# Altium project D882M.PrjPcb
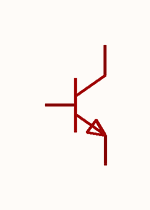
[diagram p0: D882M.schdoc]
1 sheet, 1 parts. Net scope: global (net labels, ports and power ports of the same name join across sheets).

## Sheet D882M.schdoc
size 127 x 101 mm

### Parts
Q?  d882m(range:160-320)  [TO-252-2_L6.5-W6.1-P4.58-LS10.0-TL]  (value not drawn)

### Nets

Not connected (* = marked no-connect by the designer): Q? 1(B) 3(E) 4(C)

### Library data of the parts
Q? = d882m(range:160-320): 晶体管类型:NPN;集电极电流(Ic):3A;集射极击穿电压(Vceo):30V;耗散功率(Pd):1.25W;直流电流增益(hFE):160;; Manufacturer: CJ(江苏长电/长晶); AddInBom: yes; ModelId: 6b2ea0154a284e6db98f69bccdba3606; ModelName: TO-252-2_L6.5-W6.1-H2.3-LS10.0-P4.58; ModelTransform: 255.905,390.52442,0,270,0,0,38.183,0.432,0; type: NPN; Current - Collector(Ic): 3A; Collector - Emitter Voltage VCEO: 30V; Pd - Power Dissipation: 1.25W; DC Current Gain: 160; Transition frequency(fT): 90MHz; Current - Collector Cutoff: 1uA; Vce Saturation(VCE(sat)): 500mV; Emitter-Base Voltage(Vebo): 5V; Number: 1个NPN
